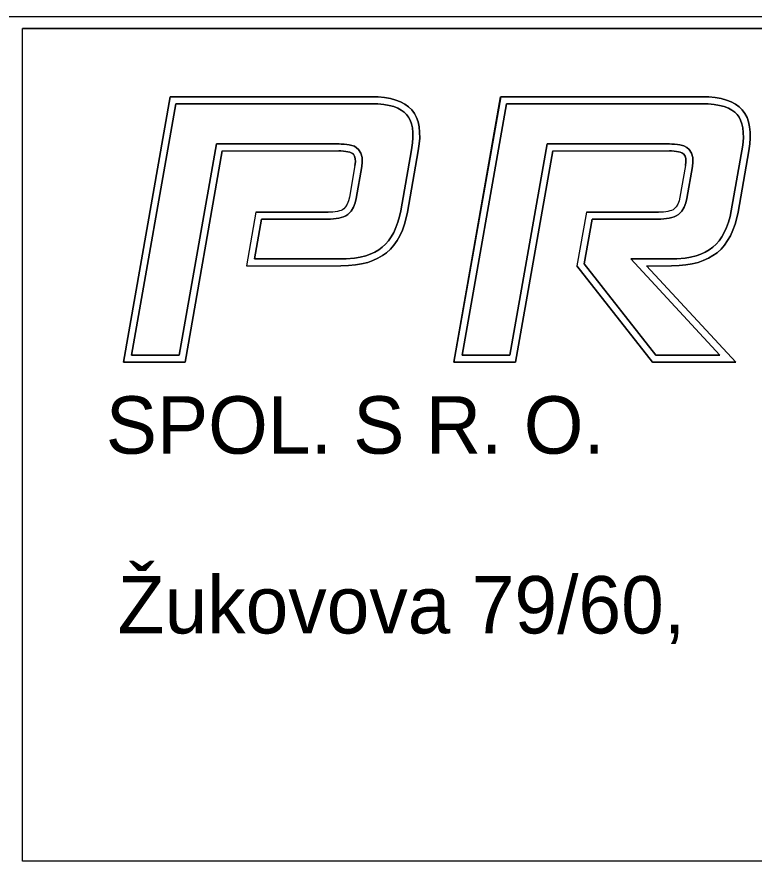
# Model space of a CAD drawing. Extents: x 249 to 564, y 49 to 194.
# Drawn here: x 531.98 to 544.18, y 71.06 to 85.02 of the extents above; entities that cross this region are included whole.
import ezdxf

# ---------------------------------------------------------------- set-up
doc = ezdxf.new("R2010")
doc.units = 0
doc.layers.add('000_rozpiska', color=7, linetype='Continuous')

msp = doc.modelspace()

# ---------------------------------------------------------------- linework, layer by layer
at = {"layer": '000_rozpiska'}
for p, q in [((559.147, 85.024), (472.697, 85.024)), ((559.147, 85.024), (472.697, 85.024)), ((559.147, 84.834), (532.072, 84.834)), ((532.072, 71.058), (532.072, 84.834)), ((533.739, 79.311), (534.513, 83.701)), ((534.512, 83.702), (537.843, 83.702)), ((539.21, 79.311), (539.983, 83.701)), ((539.982, 83.702), (543.314, 83.702)), ((535.377, 82.807), (534.761, 79.311)), ((535.377, 82.807), (537.306, 82.807)), ((538.62, 82.807), (538.442, 81.794)), ((540.848, 82.807), (540.232, 79.311)), ((540.848, 82.807), (542.777, 82.807)), ((544.091, 82.807), (543.913, 81.794)), ((537.572, 82.564), (537.481, 82.043)), ((543.043, 82.564), (542.952, 82.043)), ((535.931, 81.794), (535.775, 80.906)), ((535.931, 81.794), (537.127, 81.794)), ((541.402, 81.794), (541.246, 80.906)), ((541.402, 81.794), (542.598, 81.794)), ((535.775, 80.906), (537.339, 80.906)), ((542.498, 79.311), (541.246, 80.906)), ((542.399, 80.906), (542.81, 80.906)), ((543.874, 79.311), (542.399, 80.906)), ((534.761, 79.311), (533.739, 79.311)), ((540.232, 79.311), (539.21, 79.311)), ((543.874, 79.311), (542.498, 79.311)), ((560.382, 71.058), (532.072, 71.058))]:
    msp.add_line(p, q, dxfattribs=at)
for points in [[(532.072, 71.058), (532.072, 84.834), (559.147, 84.834)], [(538.25, 83.647), (538.161, 83.671), (538.063, 83.688), (537.956, 83.699), (537.843, 83.702), (534.513, 83.702), (533.739, 79.311), (534.761, 79.311), (535.377, 82.807), (537.306, 82.807), (537.341, 82.806), (537.383, 82.804), (537.422, 82.799), (537.456, 82.794), (537.485, 82.786), (537.51, 82.777), (537.53, 82.766), (537.546, 82.753), (537.567, 82.721), (537.578, 82.679), (537.579, 82.624), (537.572, 82.564), (537.481, 82.043), (537.466, 81.98), (537.445, 81.924), (537.418, 81.879), (537.386, 81.846), (537.366, 81.834), (537.343, 81.823), (537.314, 81.813), (537.282, 81.806), (537.245, 81.8), (537.208, 81.796), (537.163, 81.794), (537.127, 81.794), (535.931, 81.794), (535.775, 80.906), (537.339, 80.906), (537.466, 80.91), (537.579, 80.92), (537.68, 80.937), (537.783, 80.962), (537.867, 80.991), (537.953, 81.03), (538.027, 81.074), (538.095, 81.123), (538.16, 81.182), (538.217, 81.249), (538.269, 81.323), (538.316, 81.404), (538.357, 81.494), (538.393, 81.594), (538.421, 81.697), (538.442, 81.794), (538.62, 82.807), (538.637, 82.926), (538.644, 83.018), (538.642, 83.117), (538.634, 83.206), (538.616, 83.288), (538.59, 83.36), (538.556, 83.427), (538.512, 83.485), (538.46, 83.535), (538.399, 83.579), (538.328, 83.617), (538.25, 83.647)], [(537.843, 83.702), (537.956, 83.699), (538.063, 83.688), (538.161, 83.671), (538.25, 83.647), (538.328, 83.617), (538.399, 83.579), (538.46, 83.535), (538.512, 83.485), (538.556, 83.427), (538.59, 83.36), (538.616, 83.288), (538.634, 83.206), (538.642, 83.117), (538.644, 83.018), (538.637, 82.926), (538.62, 82.807)], [(544.108, 82.926), (544.115, 83.018), (544.113, 83.117), (544.105, 83.206), (544.087, 83.288), (544.061, 83.36), (544.027, 83.427), (543.983, 83.485), (543.931, 83.535), (543.87, 83.579), (543.799, 83.617), (543.721, 83.647), (543.632, 83.671), (543.534, 83.688), (543.427, 83.699), (543.314, 83.702), (539.984, 83.702), (539.21, 79.311), (540.232, 79.311), (540.848, 82.807), (542.777, 82.807), (542.812, 82.806), (542.853, 82.804), (542.893, 82.799), (542.927, 82.794), (542.956, 82.786), (542.981, 82.777), (543.001, 82.766), (543.017, 82.753), (543.038, 82.721), (543.049, 82.679), (543.05, 82.624), (543.043, 82.564), (542.952, 82.043), (542.937, 81.98), (542.916, 81.924), (542.889, 81.879), (542.857, 81.846), (542.837, 81.834), (542.814, 81.823), (542.785, 81.813), (542.753, 81.806), (542.716, 81.8), (542.679, 81.796), (542.634, 81.794), (542.598, 81.794), (541.402, 81.794), (541.246, 80.906), (542.498, 79.311), (543.874, 79.311), (542.399, 80.906), (542.81, 80.906), (542.937, 80.91), (543.05, 80.92), (543.151, 80.937), (543.254, 80.962), (543.338, 80.991), (543.424, 81.03), (543.498, 81.074), (543.566, 81.123), (543.631, 81.182), (543.688, 81.249), (543.74, 81.323), (543.787, 81.404), (543.828, 81.494), (543.864, 81.594), (543.892, 81.697), (543.913, 81.794), (544.091, 82.807), (544.108, 82.926)], [(543.314, 83.702), (543.427, 83.699), (543.534, 83.688), (543.632, 83.671), (543.721, 83.647), (543.799, 83.617), (543.87, 83.579), (543.931, 83.535), (543.983, 83.485), (544.027, 83.427), (544.061, 83.36), (544.087, 83.288), (544.105, 83.206), (544.113, 83.117), (544.115, 83.018), (544.108, 82.926), (544.091, 82.807)], [(560.382, 83.599), (560.382, 71.058), (532.072, 71.058)], [(534.608, 83.588), (537.84, 83.588), (537.949, 83.585), (538.048, 83.575), (538.137, 83.56), (538.214, 83.539), (538.281, 83.513), (538.339, 83.482), (538.387, 83.448), (538.426, 83.409), (538.459, 83.366), (538.485, 83.315), (538.506, 83.256), (538.522, 83.188), (538.528, 83.111), (538.53, 83.021), (538.524, 82.938), (538.507, 82.825), (538.33, 81.817), (538.31, 81.724), (538.284, 81.628), (538.251, 81.537), (538.214, 81.456), (538.173, 81.384), (538.127, 81.319), (538.078, 81.262), (538.023, 81.212), (537.965, 81.169), (537.9, 81.132), (537.825, 81.097), (537.75, 81.072), (537.657, 81.049), (537.564, 81.033), (537.426, 81.02), (535.91, 81.02), (536.027, 81.68), (537.129, 81.68), (537.166, 81.68), (537.216, 81.683), (537.26, 81.687), (537.303, 81.694), (537.344, 81.703), (537.385, 81.717), (537.42, 81.733), (537.457, 81.756), (537.51, 81.809), (537.548, 81.874), (537.576, 81.947), (537.593, 82.021), (537.686, 82.551), (537.693, 82.619), (537.691, 82.695), (537.672, 82.768), (537.632, 82.83), (537.567, 82.883), (537.479, 82.905), (537.438, 82.912), (537.392, 82.918), (537.345, 82.92), (537.309, 82.921), (535.281, 82.921), (534.665, 79.425), (533.875, 79.425), (534.608, 83.588)], [(538.522, 83.188), (538.506, 83.256), (538.485, 83.315), (538.459, 83.366), (538.426, 83.409), (538.387, 83.448), (538.339, 83.482), (538.281, 83.513), (538.214, 83.539), (538.137, 83.56), (538.048, 83.575), (537.949, 83.585), (537.84, 83.588), (534.608, 83.588), (533.875, 79.425), (534.665, 79.425), (535.281, 82.921), (537.309, 82.921), (537.345, 82.92), (537.392, 82.918), (537.438, 82.912), (537.479, 82.905), (537.567, 82.883), (537.632, 82.83), (537.672, 82.768), (537.691, 82.695), (537.693, 82.619), (537.686, 82.551), (537.593, 82.021), (537.576, 81.947), (537.548, 81.874), (537.51, 81.809), (537.457, 81.756), (537.42, 81.733), (537.385, 81.717), (537.344, 81.703), (537.303, 81.694), (537.26, 81.687), (537.216, 81.683), (537.166, 81.68), (537.129, 81.68), (536.027, 81.68), (535.91, 81.02), (537.426, 81.02), (537.564, 81.033), (537.657, 81.049), (537.75, 81.072), (537.825, 81.097), (537.9, 81.132), (537.965, 81.169), (538.023, 81.212), (538.078, 81.262), (538.127, 81.319), (538.173, 81.384), (538.214, 81.456), (538.251, 81.537), (538.284, 81.628), (538.31, 81.724), (538.33, 81.817), (538.507, 82.825), (538.524, 82.938), (538.53, 83.021), (538.528, 83.111), (538.522, 83.188)], [(535.281, 82.921), (534.665, 79.425), (533.875, 79.425), (534.608, 83.588), (537.84, 83.588), (537.949, 83.585), (538.048, 83.575), (538.137, 83.56), (538.214, 83.539), (538.281, 83.513), (538.339, 83.482), (538.387, 83.448), (538.426, 83.409), (538.459, 83.366), (538.485, 83.315), (538.506, 83.256), (538.522, 83.188), (538.528, 83.111), (538.53, 83.021), (538.524, 82.938), (538.507, 82.825), (538.33, 81.817), (538.31, 81.724), (538.284, 81.628), (538.251, 81.537), (538.214, 81.456), (538.173, 81.384), (538.127, 81.319), (538.078, 81.262), (538.023, 81.212), (537.965, 81.169), (537.9, 81.132), (537.825, 81.097), (537.75, 81.072), (537.657, 81.049), (537.564, 81.033), (537.426, 81.02), (535.91, 81.02), (536.027, 81.68), (537.129, 81.68), (537.166, 81.68), (537.216, 81.683), (537.26, 81.687), (537.303, 81.694), (537.344, 81.703), (537.385, 81.717), (537.42, 81.733), (537.457, 81.756), (537.51, 81.809), (537.548, 81.874), (537.576, 81.947), (537.593, 82.021), (537.686, 82.551), (537.693, 82.619), (537.691, 82.695), (537.672, 82.768), (537.632, 82.83), (537.567, 82.883), (537.479, 82.905), (537.438, 82.912), (537.392, 82.918), (537.345, 82.92), (537.309, 82.921), (535.281, 82.921)], [(540.752, 82.921), (540.136, 79.425), (539.346, 79.425), (540.079, 83.588), (543.311, 83.588), (543.42, 83.585), (543.519, 83.575), (543.608, 83.56), (543.685, 83.539), (543.752, 83.513), (543.81, 83.482), (543.858, 83.448), (543.897, 83.409), (543.93, 83.366), (543.956, 83.315), (543.977, 83.256), (543.993, 83.188), (543.999, 83.111), (544.001, 83.021), (543.992, 82.902), (543.801, 81.817), (543.781, 81.724), (543.755, 81.628), (543.722, 81.537), (543.685, 81.456), (543.644, 81.384), (543.598, 81.319), (543.549, 81.262), (543.494, 81.212), (543.436, 81.169), (543.371, 81.132), (543.296, 81.097), (543.221, 81.072), (543.128, 81.049), (543.035, 81.033), (542.897, 81.02), (542.139, 81.02), (543.613, 79.425), (542.554, 79.425), (541.367, 80.937), (541.498, 81.68), (542.6, 81.68), (542.637, 81.68), (542.687, 81.683), (542.731, 81.687), (542.774, 81.694), (542.815, 81.703), (542.856, 81.717), (542.891, 81.733), (542.928, 81.756), (542.981, 81.809), (543.019, 81.874), (543.047, 81.947), (543.063, 82.021), (543.157, 82.551), (543.164, 82.619), (543.162, 82.695), (543.143, 82.768), (543.103, 82.83), (543.065, 82.861), (543.013, 82.889), (542.95, 82.905), (542.909, 82.912), (542.863, 82.918), (542.816, 82.92), (542.78, 82.921), (540.752, 82.921)], [(543.956, 83.315), (543.93, 83.366), (543.897, 83.409), (543.858, 83.448), (543.81, 83.482), (543.752, 83.513), (543.685, 83.539), (543.608, 83.56), (543.519, 83.575), (543.42, 83.585), (543.311, 83.588), (540.079, 83.588), (539.346, 79.425), (540.136, 79.425), (540.752, 82.921), (542.78, 82.921), (542.816, 82.92), (542.863, 82.918), (542.909, 82.912), (542.95, 82.905), (543.013, 82.889), (543.065, 82.861), (543.103, 82.83), (543.143, 82.768), (543.162, 82.695), (543.164, 82.619), (543.157, 82.551), (543.063, 82.021), (543.047, 81.947), (543.019, 81.874), (542.981, 81.809), (542.928, 81.756), (542.891, 81.733), (542.856, 81.717), (542.815, 81.703), (542.774, 81.694), (542.731, 81.687), (542.687, 81.683), (542.637, 81.68), (542.6, 81.68), (541.498, 81.68), (541.367, 80.937), (542.554, 79.425), (543.613, 79.425), (542.139, 81.02), (542.897, 81.02), (543.035, 81.033), (543.128, 81.049), (543.221, 81.072), (543.296, 81.097), (543.371, 81.132), (543.436, 81.169), (543.494, 81.212), (543.549, 81.262), (543.598, 81.319), (543.644, 81.384), (543.685, 81.456), (543.722, 81.537), (543.755, 81.628), (543.781, 81.724), (543.801, 81.817), (543.992, 82.902), (544.001, 83.021), (543.999, 83.111), (543.993, 83.188), (543.977, 83.256), (543.956, 83.315)], [(540.752, 82.921), (540.136, 79.425), (539.346, 79.425), (540.079, 83.588), (543.311, 83.588), (543.42, 83.585), (543.519, 83.575), (543.608, 83.56), (543.685, 83.539), (543.752, 83.513), (543.81, 83.482), (543.858, 83.448), (543.897, 83.409), (543.93, 83.366), (543.956, 83.315), (543.977, 83.256), (543.993, 83.188), (543.999, 83.111), (544.001, 83.021), (543.992, 82.902), (543.801, 81.817), (543.781, 81.724), (543.755, 81.628), (543.722, 81.537), (543.685, 81.456), (543.644, 81.384), (543.598, 81.319), (543.549, 81.262), (543.494, 81.212), (543.436, 81.169), (543.371, 81.132), (543.296, 81.097), (543.221, 81.072), (543.128, 81.049), (543.035, 81.033), (542.897, 81.02), (542.139, 81.02), (543.613, 79.425), (542.554, 79.425), (541.367, 80.937), (541.498, 81.68), (542.6, 81.68), (542.637, 81.68), (542.687, 81.683), (542.731, 81.687), (542.774, 81.694), (542.815, 81.703), (542.856, 81.717), (542.891, 81.733), (542.928, 81.756), (542.981, 81.809), (543.019, 81.874), (543.047, 81.947), (543.063, 82.021), (543.157, 82.551), (543.164, 82.619), (543.162, 82.695), (543.143, 82.768), (543.103, 82.83), (543.065, 82.861), (543.013, 82.889), (542.95, 82.905), (542.909, 82.912), (542.863, 82.918), (542.816, 82.92), (542.78, 82.921), (540.752, 82.921)], [(537.485, 82.786), (537.456, 82.794), (537.422, 82.799), (537.383, 82.804), (537.341, 82.806), (537.306, 82.807)], [(537.572, 82.564), (537.579, 82.624), (537.578, 82.679), (537.567, 82.721), (537.546, 82.753), (537.53, 82.766), (537.51, 82.777), (537.485, 82.786)], [(542.956, 82.786), (542.927, 82.794), (542.893, 82.799), (542.853, 82.804), (542.812, 82.806), (542.777, 82.807)], [(543.043, 82.564), (543.05, 82.624), (543.049, 82.679), (543.038, 82.721), (543.017, 82.753), (543.001, 82.766), (542.981, 82.777), (542.956, 82.786)], [(537.481, 82.043), (537.466, 81.98), (537.445, 81.924), (537.418, 81.879), (537.386, 81.846), (537.366, 81.834), (537.343, 81.823), (537.314, 81.813), (537.282, 81.806), (537.245, 81.8), (537.208, 81.796), (537.163, 81.794), (537.127, 81.794)], [(542.952, 82.043), (542.937, 81.98), (542.916, 81.924), (542.889, 81.879), (542.857, 81.846), (542.837, 81.834), (542.814, 81.823), (542.785, 81.813), (542.753, 81.806), (542.716, 81.8), (542.679, 81.796), (542.634, 81.794), (542.598, 81.794)], [(538.442, 81.794), (538.421, 81.697), (538.393, 81.594), (538.357, 81.494), (538.316, 81.404), (538.269, 81.323), (538.217, 81.249), (538.16, 81.182), (538.095, 81.123), (538.027, 81.074), (537.953, 81.03), (537.867, 80.991), (537.783, 80.962), (537.68, 80.937), (537.579, 80.92), (537.466, 80.91), (537.339, 80.906)], [(543.913, 81.794), (543.892, 81.697), (543.864, 81.594), (543.828, 81.494), (543.787, 81.404), (543.74, 81.323), (543.688, 81.249), (543.631, 81.182), (543.566, 81.123), (543.498, 81.074), (543.424, 81.03), (543.338, 80.991), (543.254, 80.962), (543.151, 80.937), (543.05, 80.92), (542.937, 80.91), (542.81, 80.906)]]:
    msp.add_lwpolyline(points, dxfattribs=at)

# ---------------------------------------------------------------- texts
for s, p in [('SPOL. S R. O.', (533.448, 77.798)), ('Žukovova 79/60, ', (533.645, 74.824))]:
    msp.add_text(s, height=0.95, dxfattribs=at).set_placement(p)

doc.saveas('drawing.dxf')
